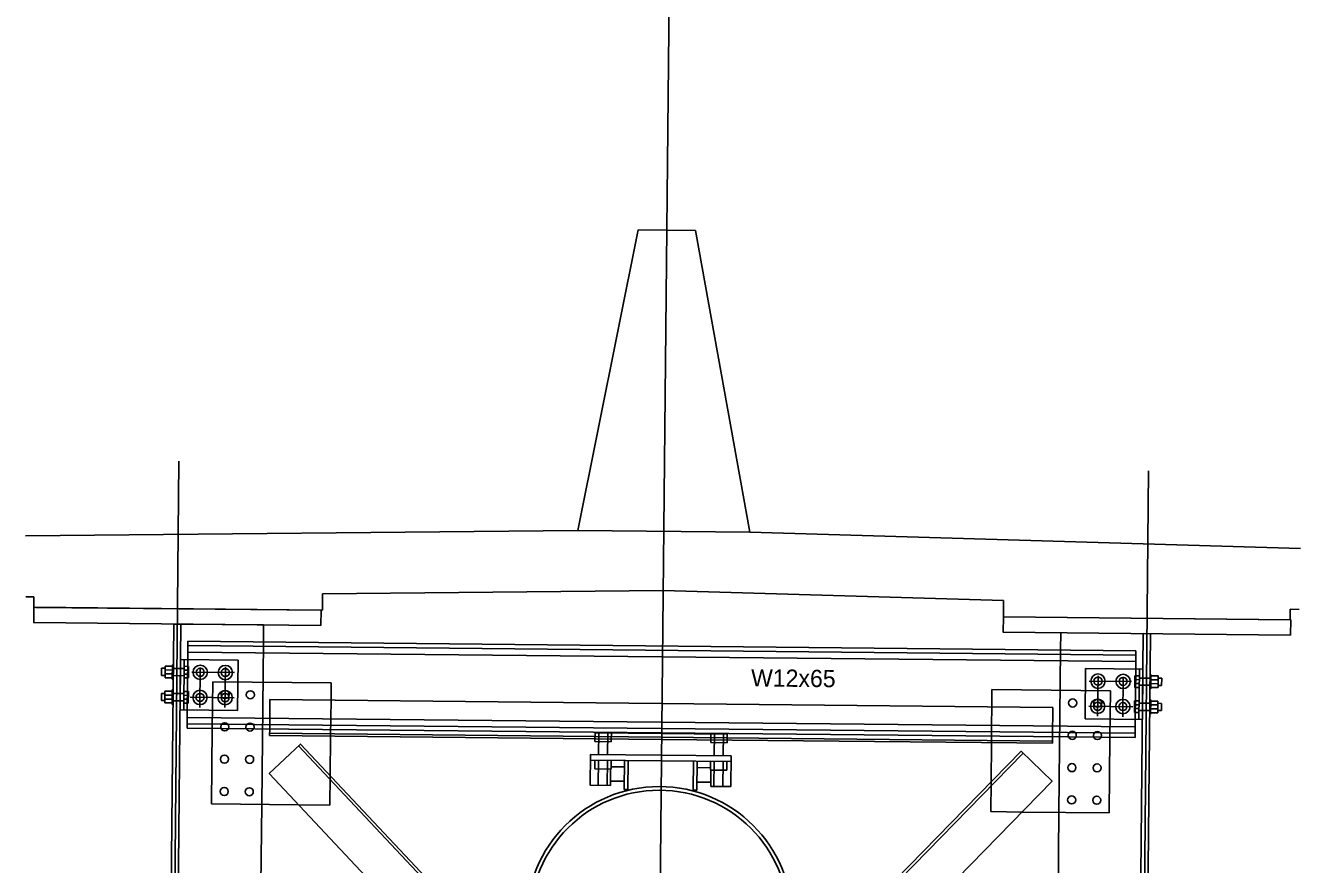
# Model space of a CAD drawing. Extents: x 632312 to 632885, y 378199 to 378534.
# Drawn here: x 632526.7 to 632541.49, y 378449.47 to 378459.2 of the extents above; entities that cross this region are included whole.
import ezdxf

# ---------------------------------------------------------------- set-up
doc = ezdxf.new("R2010")
doc.units = 0
for name, color, linetype in [('B_Boring', 7, 'Continuous'), ('B_Boring Annot', 7, 'Continuous'), ('R_Border_Divider', 7, 'Continuous'), ('R_Proposed Const Limits Cut', 7, 'Continuous'), ('R_Road Edge of Shoulder', 7, 'Continuous'), ('R_Shade Removal', 7, 'Continuous'), ('R_Wall', 7, 'Continuous'), ('SHT_Dimensions', 7, 'Continuous')]:
    doc.layers.add(name, color=color, linetype=linetype)

msp = doc.modelspace()

# ---------------------------------------------------------------- linework, layer by layer
at = {"layer": 'B_Boring'}
for p, q in [((632538.71, 378451.955), (632538.712, 378452.154)), ((632528.583, 378451.843), (632528.586, 378452.056)), ((632539.585, 378451.896), (632528.585, 378452.005)), ((632539.585, 378451.946), (632528.586, 378452.056)), ((632539.583, 378451.734), (632539.585, 378451.946)), ((632528.28, 378451.742), (632528.28, 378451.659)), ((632528.322, 378451.742), (632528.28, 378451.742)), ((632528.322, 378451.768), (632528.321, 378451.632)), ((632528.406, 378451.767), (632528.322, 378451.768)), ((632528.405, 378451.722), (632528.322, 378451.723)), ((632528.406, 378451.783), (632528.404, 378451.616)), ((632528.416, 378451.783), (632528.406, 378451.783)), ((632528.416, 378451.783), (632528.415, 378451.616)), ((632528.494, 378451.261), (632528.5, 378451.844)), ((632528.5, 378451.844), (632529.167, 378451.838)), ((632528.536, 378451.26), (632528.542, 378451.844)), ((632528.541, 378451.766), (632528.54, 378451.63)), ((632528.541, 378451.766), (632528.593, 378451.765)), ((632528.541, 378451.721), (632528.593, 378451.72)), ((632528.593, 378451.765), (632528.592, 378451.63)), ((632529.167, 378451.838), (632529.161, 378451.254)), ((632539, 378451.74), (632538.994, 378451.157)), ((632539.666, 378451.733), (632539, 378451.74)), ((632539.619, 378451.15), (632539.625, 378451.734)), ((632539.66, 378451.15), (632539.666, 378451.733)), ((632528.321, 378451.658), (632528.28, 378451.659)), ((632528.405, 378451.677), (632528.321, 378451.678)), ((632528.404, 378451.632), (632528.321, 378451.632)), ((632528.415, 378451.616), (632528.404, 378451.616)), ((632528.54, 378451.675), (632528.592, 378451.675)), ((632528.54, 378451.63), (632528.592, 378451.63)), ((632530.248, 378451.572), (632530.248, 378451.572)), ((632539.572, 378451.656), (632539.57, 378451.521)), ((632539.623, 378451.61), (632539.571, 378451.611)), ((632539.623, 378451.565), (632539.571, 378451.566)), ((632539.624, 378451.655), (632539.572, 378451.656)), ((632539.624, 378451.655), (632539.622, 378451.52)), ((632539.749, 378451.67), (632539.747, 378451.503)), ((632539.749, 378451.67), (632539.759, 378451.67)), ((632539.759, 378451.67), (632539.758, 378451.503)), ((632539.758, 378451.564), (632539.842, 378451.563)), ((632539.759, 378451.654), (632539.843, 378451.653)), ((632539.759, 378451.609), (632539.842, 378451.608)), ((632539.843, 378451.653), (632539.841, 378451.518)), ((632539.842, 378451.627), (632539.884, 378451.627)), ((632539.884, 378451.627), (632539.883, 378451.544)), ((632528.277, 378451.451), (632528.277, 378451.367)), ((632528.319, 378451.45), (632528.277, 378451.451)), ((632528.319, 378451.476), (632528.318, 378451.341)), ((632528.403, 378451.475), (632528.319, 378451.476)), ((632528.402, 378451.43), (632528.319, 378451.431)), ((632528.403, 378451.491), (632528.401, 378451.324)), ((632528.413, 378451.491), (632528.403, 378451.491)), ((632528.413, 378451.491), (632528.412, 378451.324)), ((632528.538, 378451.474), (632528.537, 378451.339)), ((632528.538, 378451.474), (632528.59, 378451.473)), ((632528.538, 378451.429), (632528.59, 378451.428)), ((632528.59, 378451.473), (632528.589, 378451.338)), ((632537.914, 378451.495), (632537.914, 378451.495)), ((632539.622, 378451.52), (632539.57, 378451.521)), ((632539.747, 378451.503), (632539.758, 378451.503)), ((632539.758, 378451.519), (632539.841, 378451.518)), ((632539.841, 378451.544), (632539.883, 378451.544)), ((632528.318, 378451.367), (632528.277, 378451.367)), ((632528.402, 378451.385), (632528.318, 378451.386)), ((632528.401, 378451.34), (632528.318, 378451.341)), ((632528.412, 378451.324), (632528.401, 378451.324)), ((632529.161, 378451.254), (632528.494, 378451.261)), ((632528.537, 378451.384), (632528.589, 378451.383)), ((632528.537, 378451.339), (632528.589, 378451.338)), ((632528.578, 378451.26), (632528.576, 378451.048)), ((632539.569, 378451.364), (632539.567, 378451.229)), ((632539.62, 378451.319), (632539.568, 378451.319)), ((632539.62, 378451.274), (632539.568, 378451.274)), ((632539.621, 378451.364), (632539.569, 378451.364)), ((632539.621, 378451.364), (632539.62, 378451.228)), ((632539.746, 378451.378), (632539.744, 378451.212)), ((632539.746, 378451.378), (632539.756, 378451.378)), ((632539.756, 378451.378), (632539.755, 378451.211)), ((632539.755, 378451.272), (632539.839, 378451.271)), ((632539.756, 378451.362), (632539.84, 378451.362)), ((632539.756, 378451.317), (632539.839, 378451.317)), ((632539.84, 378451.362), (632539.838, 378451.226)), ((632539.839, 378451.336), (632539.881, 378451.335)), ((632539.881, 378451.335), (632539.88, 378451.252)), ((632538.994, 378451.157), (632539.66, 378451.15)), ((632539.62, 378451.228), (632539.567, 378451.229)), ((632539.577, 378451.151), (632539.575, 378450.938)), ((632539.744, 378451.212), (632539.755, 378451.211)), ((632539.755, 378451.227), (632539.838, 378451.226)), ((632539.839, 378451.252), (632539.88, 378451.252)), ((632539.576, 378450.989), (632528.576, 378451.098)), ((632539.575, 378450.938), (632528.576, 378451.048)), ((632528.858, 378450.169), (632528.867, 378451.045)), ((632529.534, 378451.038), (632529.533, 378450.962)), ((632529.533, 378450.962), (632534.075, 378450.917)), ((632533.308, 378450.893), (632533.309, 378451.001)), ((632534.841, 378450.978), (632533.309, 378450.993)), ((632533.349, 378450.74), (632533.352, 378451)), ((632533.454, 378450.739), (632533.456, 378450.999)), ((632533.497, 378450.891), (632533.499, 378450.999)), ((632534.651, 378450.88), (632534.652, 378450.987)), ((632534.692, 378450.727), (632534.694, 378450.987)), ((632534.796, 378450.726), (632534.799, 378450.986)), ((632534.84, 378450.878), (632534.841, 378450.985)), ((632533.308, 378450.893), (632533.497, 378450.891)), ((632534.075, 378450.917), (632538.616, 378450.872)), ((632534.84, 378450.878), (632534.651, 378450.88)), ((632538.616, 378450.872), (632538.617, 378450.948)), ((632539.275, 378450.065), (632539.283, 378450.941)), ((632533.253, 378450.386), (632533.256, 378450.741)), ((632533.256, 378450.741), (632534.889, 378450.725)), ((632533.256, 378450.678), (632534.888, 378450.662)), ((632533.305, 378450.575), (632533.306, 378450.677)), ((632533.345, 378450.385), (632533.348, 378450.677)), ((632533.45, 378450.384), (632533.453, 378450.676)), ((632533.494, 378450.573), (632533.495, 378450.675)), ((632533.647, 378450.338), (632533.651, 378450.674)), ((632533.688, 378450.338), (632533.692, 378450.673)), ((632534.449, 378450.33), (632534.452, 378450.666)), ((632534.49, 378450.33), (632534.493, 378450.666)), ((632534.648, 378450.562), (632534.649, 378450.664)), ((632534.688, 378450.372), (632534.691, 378450.664)), ((632534.793, 378450.371), (632534.796, 378450.662)), ((632534.837, 378450.56), (632534.838, 378450.662)), ((632534.885, 378450.37), (632534.889, 378450.725)), ((632533.305, 378450.575), (632533.494, 378450.573)), ((632533.489, 378450.573), (632533.487, 378450.384)), ((632533.65, 378450.599), (632533.495, 378450.6)), ((632534.493, 378450.591), (632534.648, 378450.589)), ((632534.837, 378450.56), (632534.648, 378450.562)), ((632534.653, 378450.562), (632534.651, 378450.372)), ((632533.487, 378450.384), (632533.253, 378450.386)), ((632533.648, 378450.431), (632533.488, 378450.433)), ((632534.491, 378450.423), (632534.652, 378450.421)), ((632534.651, 378450.372), (632534.885, 378450.37)), ((632533.647, 378450.338), (632533.688, 378450.338)), ((632534.49, 378450.33), (632534.449, 378450.33)), ((632529.869, 378450.159), (632528.858, 378450.169)), ((632538.264, 378450.075), (632539.275, 378450.065)), ((632538.645, 378445.387), (632538.691, 378450.071))]:
    msp.add_line(p, q, dxfattribs=at)
for points in [[(632530.129, 378452.239), (632530.131, 378452.417), (632526.798, 378452.45), (632526.796, 378452.273)], [(632541.379, 378452.128), (632541.38, 378452.305), (632538.047, 378452.338), (632538.045, 378452.161)], [(632528.385, 378440.256), (632528.302, 378440.257), (632528.421, 378452.256), (632528.504, 378452.256)], [(632539.634, 378440.144), (632539.551, 378440.145), (632539.67, 378452.145), (632539.754, 378452.144)]]:
    msp.add_lwpolyline(points, close=True, dxfattribs=at)
for points in [[(632529.461, 378452.047), (632529.463, 378452.246), (632528.504, 378452.256), (632528.385, 378440.256), (632529.343, 378440.247), (632529.344, 378440.372)], [(632532.003, 378447.885), (632529.529, 378450.521), (632529.893, 378450.863), (632532.01, 378448.608)], [(632530.241, 378450.955), (632530.237, 378450.497)], [(632537.908, 378450.879), (632537.903, 378450.421)], [(632534.834, 378446.563), (632538.612, 378450.431), (632538.254, 378450.78), (632534.839, 378447.284)], [(632529.433, 378449.229), (632529.442, 378450.163)]]:
    msp.add_lwpolyline(points, dxfattribs=at)
for centre, radius in [((632528.728, 378451.696), 0.0469), ((632529.019, 378451.693), 0.0469), ((632539.144, 378451.593), 0.0469), ((632539.436, 378451.59), 0.0469), ((632528.725, 378451.404), 0.0469), ((632529.017, 378451.438), 0.0469), ((632529.017, 378451.402), 0.0469), ((632529.309, 378451.435), 0.0469), ((632538.85, 378451.34), 0.0469), ((632539.141, 378451.301), 0.0469), ((632539.141, 378451.337), 0.0469), ((632539.433, 378451.298), 0.0469), ((632529.013, 378451.063), 0.0469), ((632529.305, 378451.06), 0.0469), ((632538.846, 378450.965), 0.0469), ((632539.138, 378450.962), 0.0469), ((632529.009, 378450.688), 0.0469), ((632529.301, 378450.685), 0.0469), ((632538.842, 378450.59), 0.0469), ((632539.134, 378450.587), 0.0469), ((632534.054, 378448.828), 1.542), ((632529.006, 378450.313), 0.0469), ((632529.297, 378450.31), 0.0469), ((632534.054, 378448.828), 1.5), ((632538.839, 378450.215), 0.0469), ((632539.13, 378450.212), 0.0469)]:
    msp.add_circle(centre, radius, dxfattribs=at)
at = {"layer": 'B_Boring Annot'}
for p, q in [((632533.108, 378453.342), (632533.808, 378456.828)), ((632533.808, 378456.828), (632534.473, 378456.822)), ((632534.473, 378456.822), (632535.104, 378453.322)), ((632533.108, 378453.342), (632526.701, 378453.278)), ((632535.104, 378453.322), (632541.494, 378453.131)), ((632530.148, 378452.605), (632530.146, 378452.416)), ((632534.099, 378452.645), (632530.148, 378452.605)), ((632534.099, 378452.645), (632538.048, 378452.527)), ((632526.799, 378452.572), (632526.704, 378452.571)), ((632526.798, 378452.45), (632526.799, 378452.572)), ((632530.146, 378452.416), (632526.819, 378452.449)), ((632538.048, 378452.527), (632538.047, 378452.338)), ((632538.047, 378452.338), (632541.373, 378452.305)), ((632541.373, 378452.305), (632541.374, 378452.427)), ((632541.374, 378452.427), (632541.477, 378452.424))]:
    msp.add_line(p, q, dxfattribs=at)
at = {"layer": 'R_Border_Divider'}
msp.add_line((632533.108, 378453.342), (632535.104, 378453.322), dxfattribs=at)
at = {"layer": 'R_Proposed Const Limits Cut'}
for p, q in [((632529.461, 378452.047), (632529.442, 378450.163)), ((632539.584, 378451.821), (632528.584, 378451.931)), ((632538.691, 378450.071), (632538.71, 378451.955)), ((632528.541, 378451.74), (632528.416, 378451.741)), ((632528.578, 378451.26), (632528.583, 378451.843)), ((632539.577, 378451.151), (632539.583, 378451.734)), ((632528.54, 378451.656), (632528.415, 378451.658)), ((632528.867, 378451.045), (632528.873, 378451.585)), ((632528.873, 378451.585), (632530.248, 378451.572)), ((632530.248, 378451.572), (632530.246, 378451.372)), ((632539.624, 378451.629), (632539.749, 378451.628)), ((632528.538, 378451.448), (632528.413, 378451.449)), ((632537.908, 378450.879), (632537.914, 378451.495)), ((632539.289, 378451.482), (632537.914, 378451.495)), ((632539.289, 378451.482), (632539.283, 378450.941)), ((632539.623, 378451.546), (632539.748, 378451.545)), ((632528.537, 378451.365), (632528.412, 378451.366)), ((632529.534, 378451.038), (632529.537, 378451.379)), ((632538.62, 378451.288), (632529.537, 378451.379)), ((632530.241, 378450.955), (632530.246, 378451.372)), ((632538.617, 378450.948), (632538.62, 378451.288)), ((632539.62, 378451.254), (632539.745, 378451.253)), ((632539.621, 378451.338), (632539.746, 378451.337)), ((632539.576, 378451.063), (632528.577, 378451.173)), ((632538.616, 378450.898), (632529.533, 378450.988)), ((632529.87, 378450.842), (632538.502, 378441.646)), ((632538.276, 378450.758), (632529.464, 378441.735)), ((632530.237, 378450.497), (632530.233, 378450.155)), ((632537.903, 378450.421), (632537.9, 378450.079)), ((632529.869, 378450.159), (632530.233, 378450.155)), ((632538.264, 378450.075), (632537.9, 378450.079))]:
    msp.add_line(p, q, dxfattribs=at)
for centre in [(632528.728, 378451.696), (632529.019, 378451.693), (632539.144, 378451.593), (632539.436, 378451.59), (632528.725, 378451.404), (632529.017, 378451.402), (632539.141, 378451.301), (632539.433, 378451.298)]:
    msp.add_circle(centre, 0.0833, dxfattribs=at)
at = {"layer": 'R_Road Edge of Shoulder'}
msp.add_line((632533.931, 378435.766), (632534.261, 378468.942), dxfattribs=at)
at = {"layer": 'R_Shade Removal'}
for p, q in [((632528.332, 378439.08), (632528.481, 378454.145)), ((632539.581, 378438.968), (632539.731, 378454.033))]:
    msp.add_line(p, q, dxfattribs=at)
at = {"layer": 'R_Wall'}
for p, q in [((632528.728, 378451.75), (632528.724, 378451.287)), ((632529.02, 378451.754), (632529.015, 378451.289)), ((632529.124, 378451.692), (632528.629, 378451.697)), ((632539.04, 378451.594), (632539.534, 378451.589)), ((632539.145, 378451.653), (632539.14, 378451.188)), ((632539.436, 378451.644), (632539.432, 378451.181)), ((632529.121, 378451.401), (632528.611, 378451.406)), ((632539.037, 378451.302), (632539.547, 378451.297))]:
    msp.add_line(p, q, dxfattribs=at)

# ---------------------------------------------------------------- texts
at = {"layer": 'SHT_Dimensions'}
msp.add_text('W12x65', height=0.2, rotation=359.4304, dxfattribs=at).set_placement((632535.118, 378451.532))

doc.saveas('drawing.dxf')
